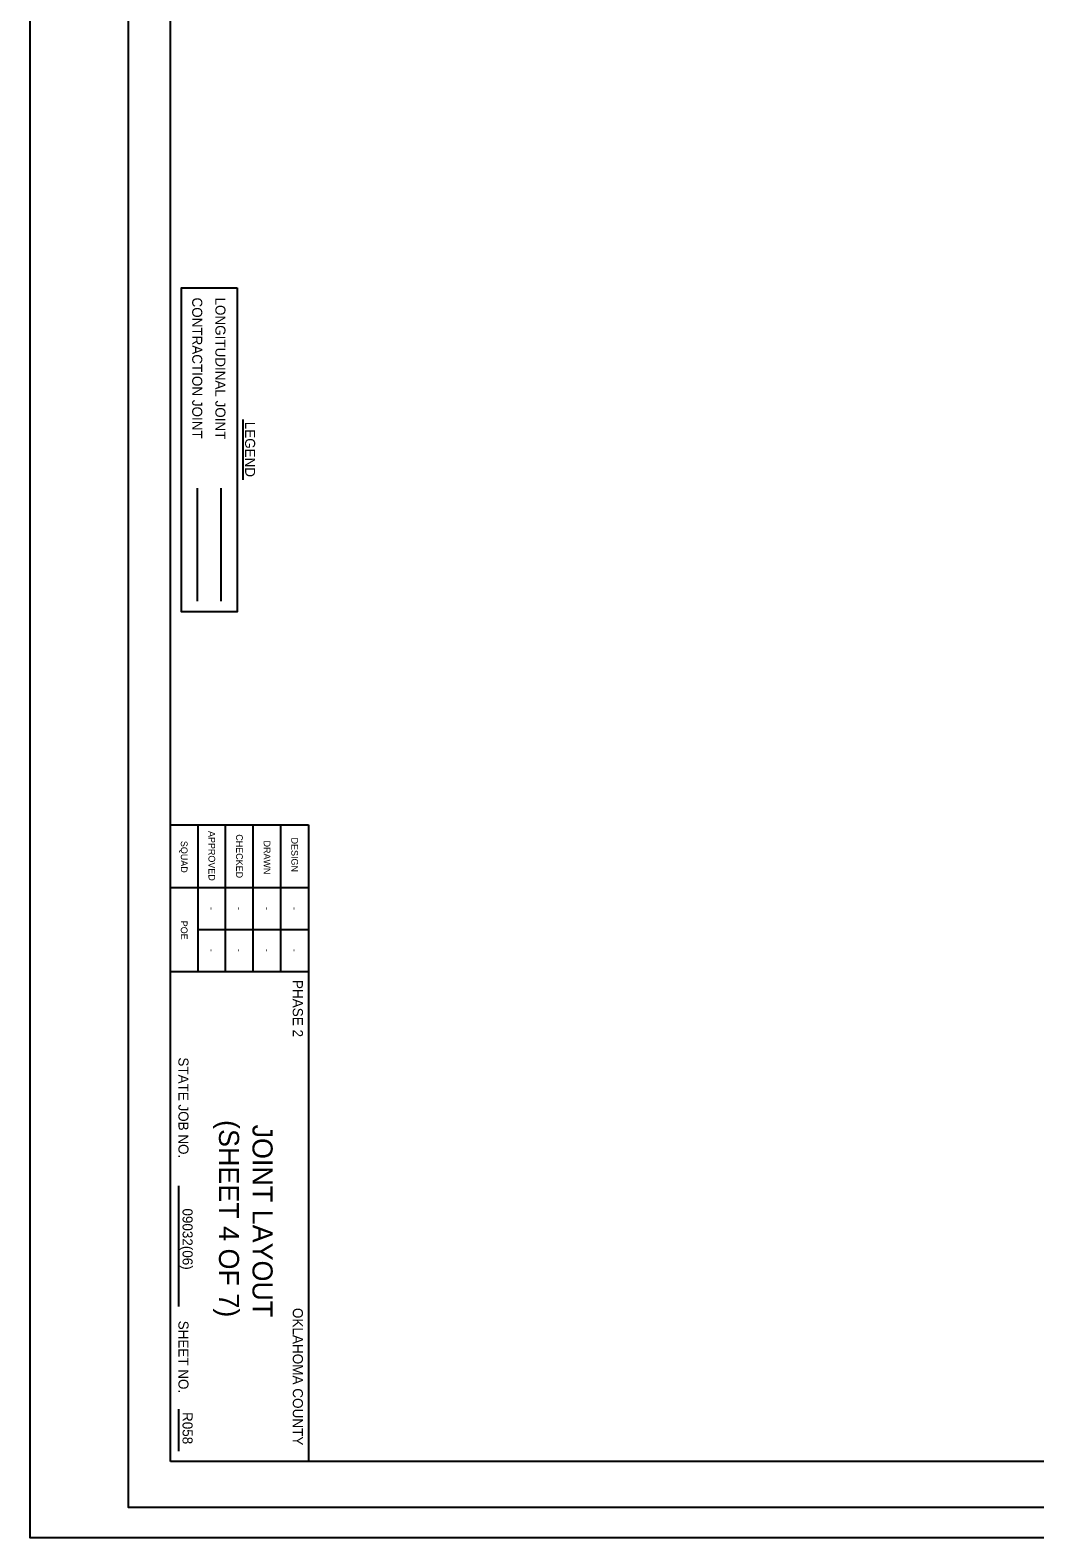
# Model space of a CAD drawing. Extents: x 2150474 to 2151194, y 142872 to 143952.
# Drawn here: x 2150474 to 2150834, y 142872 to 143412 of the extents above; entities that cross this region are included whole.
import ezdxf

# ---------------------------------------------------------------- set-up
doc = ezdxf.new("R2010")
doc.units = 0
for name, color, linetype in [('PR_Align_1_PI_Curve', 7, 'Continuous'), ('PR_Align_4', 7, 'Continuous'), ('PR_Align_4_Sta', 7, 'Continuous'), ('PR_Align_Ramp_A_PI_Curve', 7, 'Continuous'), ('PR_Align_Ramp_G_Leader', 7, 'Continuous'), ('PR_Align_Ramp_G_Txt', 7, 'Continuous'), ('PR_Align_Ramp_L_Txt', 7, 'Continuous'), ('PR_Align_Service_B_PC', 7, 'Continuous')]:
    doc.layers.add(name, color=color, linetype=linetype)

msp = doc.modelspace()

# ---------------------------------------------------------------- linework, layer by layer
at = {"layer": 'PR_Align_1_PI_Curve'}
msp.add_line((2150549.86, 143272.56), (2150549.86, 143250.95), dxfattribs=at)
msp.add_lwpolyline([(2150547.79, 143319.76), (2150547.79, 143203.75), (2150527.84, 143203.75), (2150527.84, 143319.76)], close=True, dxfattribs=at)
at = {"layer": 'PR_Align_4'}
for p, q in [((2150523.88, 143104.92), (2150573.41, 143104.92)), ((2150533.79, 143089.92), (2150573.41, 143089.92)), ((2150526.77, 142998.1), (2150526.77, 142954.89)), ((2150526.77, 142918.15), (2150526.77, 142903.08))]:
    msp.add_line(p, q, dxfattribs=at)
for points in [[(2150533.78, 143074.92), (2150533.78, 143127.42)], [(2150543.68, 143074.92), (2150543.68, 143127.42)], [(2150553.58, 143074.92), (2150553.58, 143127.42)], [(2150563.48, 143074.92), (2150563.48, 143127.42)]]:
    msp.add_lwpolyline(points, dxfattribs=at)
at = {"layer": 'PR_Align_Ramp_A_PI_Curve'}
msp.add_lwpolyline([(2151168.88, 143902.92), (2151168.88, 142882.92), (2150508.88, 142882.92), (2150508.88, 143902.92)], close=True, dxfattribs=at)
at = {"layer": 'PR_Align_Ramp_G_Leader'}
msp.add_lwpolyline([(2151193.63, 143952.04), (2151193.63, 142872.04), (2150473.63, 142872.04), (2150473.63, 143952.04)], close=True, dxfattribs=at)
at = {"layer": 'PR_Align_Ramp_G_Txt'}
for p, q in [((2150523.88, 143127.42), (2150573.38, 143127.42)), ((2150573.38, 143127.42), (2150573.39, 142899.42)), ((2150523.88, 143074.92), (2150573.41, 143074.92))]:
    msp.add_line(p, q, dxfattribs=at)
msp.add_lwpolyline([(2150523.88, 142899.42), (2150523.88, 143844.42), (2151153.88, 143844.42), (2151153.88, 142899.42)], close=True, dxfattribs=at)
at = {"layer": 'PR_Align_Ramp_L_Txt'}
msp.add_line((2150541.92, 143247.96), (2150541.92, 143207.53), dxfattribs=at)
at = {"layer": 'PR_Align_Service_B_PC'}
msp.add_lwpolyline([(2150533.5, 143247.96), (2150533.5, 143207.53)], dxfattribs=at)

# ---------------------------------------------------------------- texts
at = {"layer": 'PR_Align_1_PI_Curve'}
for s, p in [('CONTRACTION JOINT', (2150531.7, 143316.28)), ('LONGITUDINAL JOINT', (2150540.01, 143316.28)), ('LEGEND', (2150550.65, 143271.78))]:
    msp.add_text(s, height=3.6, rotation=270, dxfattribs=at).set_placement(p)
at = {"layer": 'PR_Align_4_Sta'}
for s, height, p in [('APPROVED', 2.4, (2150537.53, 143125.21)), ('CHECKED', 2.4, (2150547.43, 143124.03)), ('DESIGN', 2.4, (2150567.23, 143122.85)), ('SQUAD', 2.4, (2150527.63, 143121.67)), ('DRAWN', 2.4, (2150557.33, 143121.78)), ('-', 2.4, (2150537.52, 143098)), ('-', 2.4, (2150547.42, 143098)), ('-', 2.4, (2150557.32, 143098)), ('-', 2.4, (2150567.25, 143098)), ('POE', 2.4, (2150527.63, 143093.07)), ('-', 2.4, (2150537.52, 143083)), ('-', 2.4, (2150547.42, 143083)), ('-', 2.4, (2150557.32, 143083)), ('-', 2.4, (2150567.25, 143083)), ('PHASE 2', 3.621, (2150567.75, 143071.86)), ('STATE JOB NO.', 3.6, (2150526.77, 143044.11)), ('(SHEET 4 OF 7)', 7.2, (2150541.29, 143021.67)), ('JOINT LAYOUT', 7.2, (2150553.31, 143020.05)), ('09032(06)', 3.6, (2150528.25, 142990.02)), ('SHEET NO. ', 3.6, (2150526.77, 142949.8)), ('OKLAHOMA COUNTY', 3.6211, (2150567.75, 142954.4)), ('R058', 3.6, (2150528.25, 142917.09))]:
    msp.add_text(s, height=height, rotation=270, dxfattribs=at).set_placement(p)

doc.saveas('drawing.dxf')
